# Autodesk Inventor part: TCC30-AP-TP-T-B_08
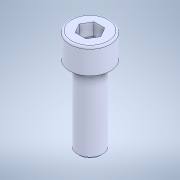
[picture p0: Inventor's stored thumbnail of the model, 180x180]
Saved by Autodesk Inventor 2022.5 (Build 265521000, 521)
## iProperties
Created: 2023-09
Part Number: TCC30-AP-TP-T-B_08
Material: 一般
Document SubType Name: Modeling
Designer: ImaoCorp
Density: 1 g/cm^3
Appearance: 既定
Author: ImaoCorp
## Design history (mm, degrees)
feature "TCC30-AP-TP-T-B_08"
node "ソリッド1"
